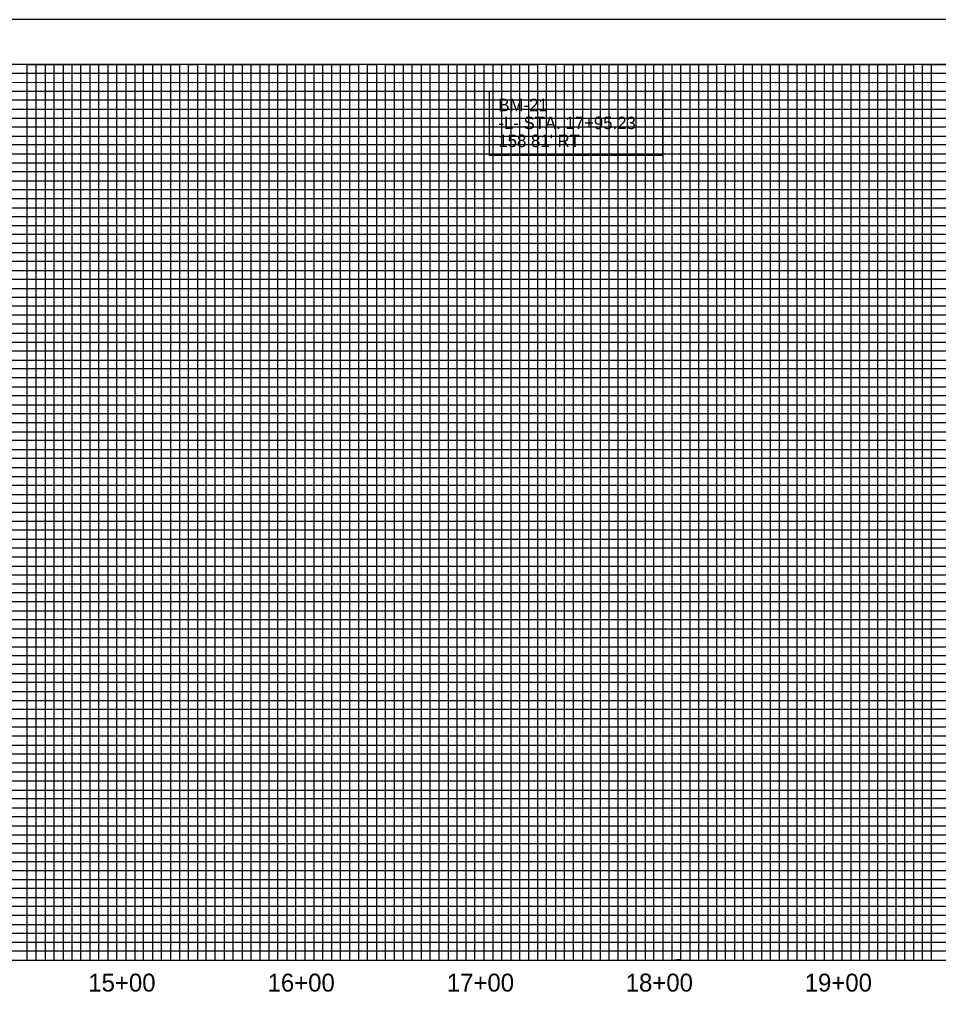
# Model space of a CAD drawing. Extents: x 1524869 to 1526553, y 501099 to 502199.
# Drawn here: x 1525527 to 1526040, y 501652 to 502199 of the extents above; entities that cross this region are included whole.
import ezdxf

# ---------------------------------------------------------------- set-up
doc = ezdxf.new("R2010")
doc.units = 0
for name, color, linetype in [('Exist Vertical Profile Horizontal Axis Label Major', 7, 'Continuous'), ('Prop Grid Mask', 7, 'Continuous'), ('Prop Vertical Profile Curve Label', 7, 'Continuous'), ('Prop VPI Label', 7, 'Continuous'), ('Sheet Layout Profile Border Port 1', 7, 'Continuous'), ('Sheet Plot Border Outside CELL', 7, 'Continuous'), ('Sheet Profile CELL', 7, 'Continuous'), ('Sheet Profile Grid Major CELL', 7, 'Continuous'), ('Sheet Profile Grid Middle CELL', 7, 'Continuous'), ('Sheet Profile Grid Minor CELL', 7, 'Continuous')]:
    doc.layers.add(name, color=color, linetype=linetype)

msp = doc.modelspace()

# ---------------------------------------------------------------- linework, layer by layer
at = {"layer": 'Prop Grid Mask'}
msp.add_lwpolyline([(1525789.18, 502158.58), (1525885.84, 502158.58), (1525885.84, 502122.61), (1525789.18, 502122.61)], close=True, dxfattribs=at)
at = {"layer": 'Sheet Layout Profile Border Port 1'}
msp.add_lwpolyline([(1525086.08, 502173.56), (1525058.64, 501673.56), (1526486.08, 501673.56), (1526486.08, 502012.51), (1526336.03, 502012.51), (1526336.08, 502173.56)], close=True, dxfattribs=at)
msp.add_lwpolyline([(1525086.08, 502173.56), (1525058.64, 501673.56), (1526486.08, 501673.56), (1526486.08, 502012.51), (1526336.03, 502012.51), (1526336.08, 502173.56)], close=True, dxfattribs=at)
at = {"layer": 'Sheet Plot Border Outside CELL'}
msp.add_lwpolyline([(1524869.08, 501098.56), (1526553.08, 501098.56), (1526553.08, 502198.56), (1524869.08, 502198.56)], close=True, dxfattribs=at)
at = {"layer": 'Sheet Profile CELL'}
msp.add_line((1525036.08, 501673.56), (1526536.08, 501673.56), dxfattribs=at)
msp.add_lwpolyline([(1526536.08, 502173.56), (1525036.08, 502173.56), (1525036.08, 501123.56), (1526536.08, 501123.56)], close=True, dxfattribs=at)
at = {"layer": 'Sheet Profile Grid Major CELL'}
for points in [[(1525486.08, 501673.56), (1525536.08, 501673.56), (1525536.08, 502173.56), (1525586.08, 502173.56), (1525586.08, 501673.56), (1525636.08, 501673.56), (1525636.08, 502173.56), (1525686.08, 502173.56), (1525686.08, 501673.56), (1525736.08, 501673.56), (1525736.08, 502173.56), (1525786.08, 502173.56), (1525786.08, 501673.56), (1525836.08, 501673.56), (1525836.08, 502173.56), (1525886.08, 502173.56), (1525886.08, 501673.56), (1525936.08, 501673.56), (1525936.08, 502173.56), (1525986.08, 502173.56), (1525986.08, 501673.56), (1526036.08, 501673.56), (1526036.08, 502173.56), (1526086.08, 502173.56)], [(1525036.08, 502123.56), (1526336.08, 502123.56)], [(1526336.08, 502073.56), (1525036.08, 502073.56), (1525036.08, 502023.56), (1526336.08, 502023.56)], [(1526536.08, 501973.56), (1525036.08, 501973.56), (1525036.08, 501923.56), (1526536.08, 501923.56)], [(1526536.08, 501873.56), (1525036.08, 501873.56), (1525036.08, 501823.56), (1526536.08, 501823.56)], [(1526536.08, 501773.56), (1525036.08, 501773.56), (1525036.08, 501773.56), (1525036.08, 501723.56), (1526536.08, 501723.56)]]:
    msp.add_lwpolyline(points, dxfattribs=at)
at = {"layer": 'Sheet Profile Grid Middle CELL'}
msp.add_line((1525036.08, 502148.56), (1526336.03, 502148.56), dxfattribs=at)
for points in [[(1525511.08, 501673.56), (1525561.08, 501673.56), (1525561.08, 502173.56), (1525611.08, 502173.56), (1525611.08, 501673.56), (1525661.08, 501673.56), (1525661.08, 501673.56), (1525661.08, 502173.56), (1525711.08, 502173.56), (1525711.08, 501673.56), (1525761.08, 501673.56), (1525761.08, 502173.56), (1525811.08, 502173.56), (1525811.08, 501673.56), (1525861.08, 501673.56), (1525861.08, 502173.56), (1525911.08, 502173.56), (1525911.08, 501673.56), (1525961.08, 501673.56), (1525961.08, 502173.56), (1526011.08, 502173.56), (1526011.08, 501673.56), (1526061.08, 501673.56)], [(1526336.08, 502098.56), (1525036.08, 502098.56), (1525036.08, 502048.56), (1526336.08, 502048.56)], [(1526536.08, 501998.56), (1525036.08, 501998.56), (1525036.08, 501948.56), (1526361.08, 501948.56)], [(1526536.08, 501898.56), (1525036.08, 501898.56), (1525036.08, 501848.56), (1526536.08, 501848.56)], [(1526536.08, 501798.56), (1525036.08, 501798.56), (1525036.08, 501748.56), (1526536.08, 501748.56)], [(1526536.08, 501698.56), (1525036.08, 501698.56)]]:
    msp.add_lwpolyline(points, dxfattribs=at)
at = {"layer": 'Sheet Profile Grid Minor CELL'}
for p, q in [((1525086.08, 502168.56), (1526187.87, 502168.56)), ((1526187.87, 502163.52), (1525086.08, 502163.21)), ((1525086.08, 502158.56), (1526336.08, 502158.56)), ((1526336.03, 502038.56), (1525086.08, 502038.56)), ((1526336.08, 502033.56), (1525086.08, 502033.56)), ((1526336.08, 502028.56), (1525086.08, 502028.56)), ((1525086.08, 502018.56), (1526336.08, 502018.56)), ((1526336.08, 502013.56), (1525086.08, 502013.56)), ((1525086.08, 502008.56), (1526486.08, 502008.56)), ((1526486.08, 501988.56), (1525086.08, 501988.56)), ((1525086.08, 501983.56), (1526486.08, 501983.56)), ((1526486.08, 501963.56), (1525086.08, 501963.56)), ((1525086.08, 501958.56), (1526486.08, 501958.56)), ((1526486.08, 501938.56), (1525086.08, 501938.56)), ((1525086.08, 501933.56), (1526486.08, 501933.56)), ((1526486.08, 501928.56), (1525086.08, 501928.56)), ((1525086.08, 501918.56), (1526486.08, 501918.56)), ((1526486.08, 501913.56), (1525086.08, 501913.56)), ((1525086.08, 501908.56), (1526486.08, 501908.56)), ((1526486.08, 501903.56), (1525086.08, 501903.56)), ((1525086.08, 501893.56), (1526486.08, 501893.56)), ((1526486.08, 501888.56), (1525086.08, 501888.56)), ((1525086.08, 501883.56), (1526486.08, 501883.56)), ((1526486.08, 501878.56), (1525086.08, 501878.56)), ((1525086.08, 501868.56), (1526486.08, 501868.56)), ((1526486.08, 501863.56), (1525086.08, 501863.56)), ((1525086.08, 501858.56), (1526486.08, 501858.56)), ((1526486.08, 501853.56), (1525086.08, 501853.56)), ((1525086.08, 501843.56), (1526486.08, 501843.56)), ((1526486.08, 501838.56), (1525086.08, 501838.56)), ((1525086.08, 501833.56), (1526486.08, 501833.56)), ((1526486.08, 501828.56), (1525086.08, 501828.56)), ((1525086.08, 501818.56), (1526486.08, 501818.56)), ((1526486.08, 501813.56), (1525086.08, 501813.56)), ((1525086.08, 501808.56), (1526486.08, 501808.56)), ((1526486.08, 501803.56), (1525086.08, 501803.56)), ((1525086.08, 501793.56), (1526486.08, 501793.56)), ((1526486.08, 501788.56), (1525086.08, 501788.56)), ((1526486.08, 501783.56), (1525086.08, 501783.56)), ((1526486.08, 501778.56), (1525086.08, 501778.56)), ((1525086.08, 501768.56), (1526486.08, 501768.56)), ((1526486.08, 501763.56), (1525086.08, 501763.56)), ((1525086.08, 501758.56), (1526486.08, 501758.56)), ((1526486.08, 501753.56), (1525086.08, 501753.56)), ((1525086.08, 501743.56), (1526486.08, 501743.56)), ((1526486.08, 501738.56), (1525086.08, 501738.56)), ((1525086.08, 501733.56), (1526486.08, 501733.56)), ((1526486.08, 501728.56), (1525086.08, 501728.56)), ((1525086.08, 501718.56), (1526486.08, 501718.56)), ((1526486.08, 501713.56), (1525086.08, 501713.56)), ((1525086.08, 501708.56), (1526486.08, 501708.56)), ((1526486.08, 501703.56), (1525086.08, 501703.56)), ((1525086.08, 501693.56), (1526486.08, 501693.56)), ((1526486.08, 501688.56), (1525086.08, 501688.56)), ((1525086.08, 501683.56), (1526486.08, 501683.56))]:
    msp.add_line(p, q, dxfattribs=at)
for points in [[(1525526.08, 501673.56), (1525531.08, 501673.56), (1525531.08, 502173.56), (1525541.08, 502173.56), (1525541.08, 501673.56), (1525546.08, 501673.56), (1525546.08, 502173.56), (1525551.08, 502173.56), (1525551.08, 501673.56), (1525556.08, 501673.56), (1525556.08, 502173.56), (1525566.08, 502173.56), (1525566.08, 501673.56), (1525571.08, 501673.56), (1525571.08, 502173.56), (1525576.08, 502173.56), (1525576.08, 501673.56), (1525581.08, 501673.56), (1525581.08, 502173.56), (1525591.08, 502173.56), (1525591.08, 501673.56), (1525596.08, 501673.56), (1525596.08, 502173.56), (1525601.08, 502173.56), (1525601.08, 501673.56), (1525606.08, 501673.56), (1525606.08, 502173.56), (1525616.08, 502173.56)], [(1525616.08, 502173.56), (1525616.08, 501673.56), (1525621.08, 501673.56), (1525621.08, 502173.56), (1525626.08, 502173.56), (1525626.08, 501673.56), (1525631.08, 501673.56), (1525631.08, 502173.56), (1525641.08, 502173.56), (1525641.08, 501673.56), (1525646.08, 501673.56), (1525646.08, 502173.56), (1525651.08, 502173.56), (1525651.08, 501673.56), (1525656.08, 501673.56), (1525656.08, 502173.56), (1525666.08, 502173.56), (1525666.08, 501673.56), (1525671.08, 501673.56), (1525671.08, 502173.56), (1525676.08, 502173.56), (1525676.08, 501673.56), (1525681.08, 501673.56), (1525681.08, 502173.56), (1525691.08, 502173.56), (1525691.08, 501673.56), (1525696.08, 501673.56), (1525696.08, 502173.56), (1525701.08, 502173.56), (1525701.08, 501673.56), (1525706.08, 501673.56), (1525706.08, 502173.56), (1525716.08, 502173.56), (1525716.08, 501673.56), (1525721.08, 501673.56), (1525721.08, 502173.56), (1525726.08, 502173.56), (1525726.08, 501673.56), (1525731.08, 501673.56), (1525731.08, 502173.56), (1525741.08, 502173.56), (1525741.08, 501673.56), (1525741.08, 501673.56), (1525746.08, 501673.56), (1525746.08, 502173.56), (1525751.08, 502173.56), (1525751.08, 501673.56), (1525756.08, 501673.56), (1525756.08, 502173.56), (1525766.08, 502173.56), (1525766.08, 501673.56), (1525771.08, 501673.56), (1525771.08, 502173.56), (1525776.08, 502173.56), (1525776.08, 501673.56), (1525781.08, 501673.56), (1525781.08, 502173.56), (1525791.08, 502173.56), (1525791.08, 501673.56), (1525796.08, 501673.56), (1525796.08, 502173.56), (1525801.08, 502173.56), (1525801.08, 501673.56), (1525806.08, 501673.56), (1525806.08, 502173.56), (1525816.08, 502173.56), (1525816.08, 501673.56), (1525821.08, 501673.56), (1525821.08, 502173.56), (1525826.08, 502173.56), (1525826.08, 501673.56), (1525831.08, 501673.56), (1525831.08, 502173.56), (1525841.08, 502173.56), (1525841.08, 501673.56), (1525846.08, 501673.56), (1525846.08, 502173.56), (1525851.08, 502173.56), (1525851.08, 501673.56), (1525856.08, 501673.56), (1525856.08, 502173.56), (1525866.08, 502173.56), (1525866.08, 501673.56), (1525871.08, 501673.56), (1525871.08, 502173.56), (1525876.08, 502173.56), (1525876.08, 501673.56), (1525881.08, 501673.56), (1525881.08, 502173.56), (1525891.08, 502173.56), (1525891.08, 501673.56), (1525895.78, 501674.11), (1525896.08, 501673.56), (1525896.08, 502173.56), (1525901.08, 502173.56), (1525901.08, 501673.56), (1525906.08, 501673.56), (1525906.08, 502173.56), (1525916.08, 502173.56), (1525916.08, 501673.56), (1525921.08, 501673.56)], [(1525921.08, 501673.56), (1525921.08, 502173.56), (1525926.08, 502173.56), (1525926.08, 501673.56), (1525931.08, 501673.56), (1525931.08, 502173.56), (1525941.08, 502173.56), (1525941.08, 501673.56), (1525946.08, 501673.56), (1525946.08, 502173.56), (1525951.08, 502173.56), (1525951.08, 501673.56), (1525956.08, 501673.56), (1525956.08, 502173.56), (1525966.08, 502173.56), (1525966.08, 501673.56), (1525971.08, 501673.56), (1525971.08, 502173.56), (1525976.08, 502173.56), (1525976.08, 501673.56), (1525981.08, 501673.56), (1525981.08, 502173.56), (1525991.08, 502173.56), (1525991.08, 501673.56), (1525996.08, 501673.56), (1525996.08, 502173.56), (1526001.08, 502173.56), (1526001.08, 501673.56), (1526006.08, 501673.56), (1526006.08, 502173.56), (1526016.08, 502173.56), (1526016.08, 501673.56), (1526021.08, 501673.56), (1526021.08, 502173.56), (1526026.08, 502173.56), (1526026.08, 501673.56), (1526031.08, 501673.56), (1526031.08, 502173.56), (1526041.08, 502173.56)], [(1526336.08, 502153.56), (1525086.08, 502153.56), (1525086.08, 502143.56), (1526336.08, 502143.56)], [(1526336.03, 502138.56), (1525086.08, 502138.56), (1525086.08, 502133.56), (1526336.08, 502133.56)], [(1526336.08, 502128.56), (1525086.08, 502128.56), (1525086.08, 502118.56), (1526336.08, 502118.56)], [(1526336.08, 502113.56), (1525086.08, 502113.56), (1525086.08, 502108.56), (1526336.08, 502108.56)], [(1526336.08, 502103.56), (1525086.08, 502103.56), (1525086.08, 502093.56), (1526336.08, 502093.56)], [(1526336.08, 502088.56), (1525086.08, 502088.56), (1525086.08, 502083.56), (1526336.08, 502083.56)], [(1526336.08, 502078.56), (1525086.08, 502078.56), (1525086.08, 502068.56), (1526336.08, 502068.56)], [(1526336.08, 502063.46), (1525086.18, 502063.46), (1525086.18, 502058.56), (1526336.08, 502058.56)], [(1526336.08, 502053.56), (1525086.08, 502053.56), (1525086.08, 502043.56), (1526336.08, 502043.56)], [(1526486.08, 502003.56), (1525086.08, 502003.56), (1525086.08, 501993.56), (1526486.08, 501993.56)], [(1526486.08, 501978.56), (1525086.08, 501978.56), (1525086.08, 501968.56), (1526486.08, 501968.56)], [(1526486.08, 501953.56), (1525086.08, 501953.56), (1525086.08, 501943.56), (1526486.08, 501943.56)], [(1526486.08, 501678.56), (1525086.08, 501678.56)]]:
    msp.add_lwpolyline(points, dxfattribs=at)

# ---------------------------------------------------------------- texts
at = {"layer": 'Exist Vertical Profile Horizontal Axis Label Major'}
for s, p in [('15+00', (1525565.17, 501656.06)), ('16+00', (1525665.28, 501656.06)), ('17+00', (1525765.39, 501656.06)), ('18+00', (1525865.28, 501656.06)), ('19+00', (1525965.25, 501656.06))]:
    msp.add_text(s, height=10, dxfattribs=at).set_placement(p)
at = {"layer": 'Prop Vertical Profile Curve Label'}
msp.add_text("158.81' RT", height=7, dxfattribs=at).set_placement((1525794.19, 502127.41))
at = {"layer": 'Prop VPI Label'}
for s, p in [('BM-21', (1525794.19, 502147.41)), ('-L- STA. 17+95.23', (1525794.19, 502137.41))]:
    msp.add_text(s, height=7, dxfattribs=at).set_placement(p)

doc.saveas('drawing.dxf')
